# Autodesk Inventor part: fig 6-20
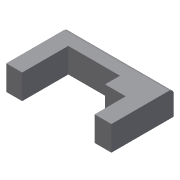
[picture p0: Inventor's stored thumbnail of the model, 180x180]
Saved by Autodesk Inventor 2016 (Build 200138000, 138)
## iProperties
Created: 2010-08
Part Number: fig 6-20
Document SubType Name: Modeling
Designer: CADSoft
Density: 1 g/cm^3
Material: Generic
Appearance: Default
Author: CADSoft
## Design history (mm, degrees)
sketch "Sketch1"
  geometry: L1 (-25.394, 25.152)-(17.03, 25.152); L2 (17.03, 25.152)-(17.03, 0); L3 (-25.394, 0)-(-25.394, 25.152); L4 (10.242, 0)-(10.242, 12.576); L5 (10.242, 12.576)-(1.879, 12.576); L6 (1.879, 12.576)-(1.879, 18.606); L7 (1.879, 18.606)-(-18.97, 18.606); L8 (-18.97, 18.606)-(-18.97, 0); L9 (17.03, 0)-(10.242, 0); L10 (-18.97, 0)-(-25.394, 0); 1 further point
  constraints: 20 end point, 6 parallel, 4 perpendicular, 1 horizontal
extrude "Extrusion1" new body sketch "Sketch1" distance "d0" = 10; taper "d1" = 0 deg
fillet "Fillet1" dims "d2" = 2
body "Solid1"
